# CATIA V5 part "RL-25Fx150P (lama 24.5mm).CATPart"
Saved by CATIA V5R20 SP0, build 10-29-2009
Part number: _RL-25Fx150P (lama 24.5mm)
Definition: NONE
Nomenclature: _RL-25Fx150P (lama 24.5mm)
Source: Unknown
Description: PART-_RL-25Fx150P (lama 24.5mm)-DESC
Bounding box of the stored display mesh (mm): x -150 to 14, y -13.5 to 13.5, z -13.5 to 13.5
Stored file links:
  C:\Users\Utente\Desktop\IO LAVORO\3D X SITO CF\X SITO\PLASTICA\RLF\RL-25Fx150P (lama 24.5mm).CATPart
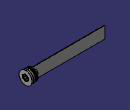
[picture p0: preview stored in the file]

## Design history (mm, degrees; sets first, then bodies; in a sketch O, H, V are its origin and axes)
Body1 "_RL-25Fx150P (lama 24.5mm)" (main body)
  Solid1: solid without history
